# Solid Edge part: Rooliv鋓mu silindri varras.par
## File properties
Author: KULL
Template: Iso Metric Part.par
Last saved by: KULL
Revision: 3
Application: Solid Edge
Accuracy: 0,990
Face Style: Model Default
Fill Style: Normal
Coef. of Thermal Exp: 0.0
Thermal Conductivity: 0.0
Specific Heat: 0.0
Modulus of Elasticity: 0.0
Poisson's Ratio: 0.0
Yield Stress: 0.0
Ultimate Stress: 0.0
Elongation: 0.0
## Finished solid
Body 1: sheet body, 1 face, 1 edge, 0 vertices.
  Faces by surface: plane 1
  Edges by curve: circle 1
Body 2: solid body, 3 faces, 2 edges, 0 vertices.
  Faces by surface: sphere 2, cylinder 1
  Edges by curve: circle 2
Bounding box of the edges (mm; curved faces can reach further): 6.000 x 117.764 x 6.000, from (-25, -57.7639, 17.8206) to (-19, 60, 23.8206).
Cylindrical faces by radius (mm): R2 x1
Spherical faces by radius (mm): R3 x2
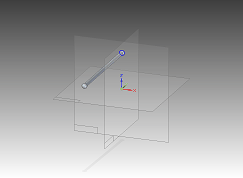
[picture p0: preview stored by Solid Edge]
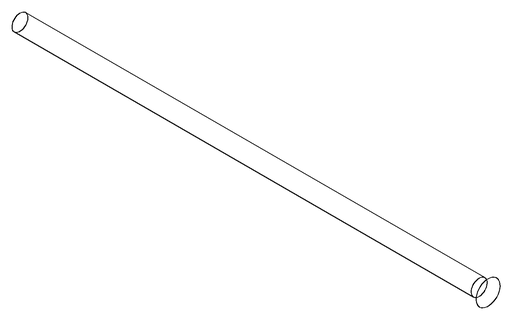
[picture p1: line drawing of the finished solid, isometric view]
